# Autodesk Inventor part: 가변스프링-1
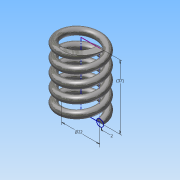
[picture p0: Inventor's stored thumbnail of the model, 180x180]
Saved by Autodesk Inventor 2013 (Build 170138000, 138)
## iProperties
Created: 2016-01
Part Number: 가변스프링-1
Material: 스테인리스강
Document SubType Name: Modeling
Designer: Administrator
Mass: 34.3346 g
Surface Area: 43.3134 cm^2
Volume: 4.24934 cm^3
Density: 8.08 g/cm^3
Author: Administrator
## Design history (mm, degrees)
sketch "스케치1"
  geometry: L1 (0, 0)-(11, 0); L2 (11, 0)-(11, 36.411); L3 (11, 36.411)-(0, 36.411); L4 (0, 36.411)-(0, 0); C1 r 2 at (11, 0)
  constraints: 8 end point, 2 parallel, 1 centre point, 1 coincident, 1 horizontal, 1 perpendicular
  dimensions: "d0" = 2 radius of C1; "d1" = 22 diameter of L2 L4; "d2" = 36.4112 distance between parallel lines of L3 L1 (derived)
feature "코일1" sketch "스케치1" pitch "d3" = 10; turns "d5" = 5; dims "d4" = 36.4112 (= d2), "d6" = 0, angle "d7" = 90 deg, angle "d8" = 90 deg, "d9" = 0, "d10" = 0
feature "분할1"
node "작업 평면1"
feature "분할2"
node "솔리드1"
other parameters: "d11" = 90 deg
